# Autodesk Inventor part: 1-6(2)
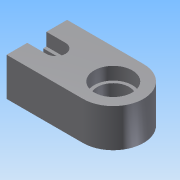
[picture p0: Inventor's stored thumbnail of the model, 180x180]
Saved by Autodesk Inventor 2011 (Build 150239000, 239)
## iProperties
Created: 2014-02
Part Number: 1-6(2)
Document SubType Name: Modeling
Designer: Administrator
Density: 1 g/cm^3
Author: Administrator
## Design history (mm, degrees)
sketch "草图1"
  geometry: L1 (-12, 9.5)-(12, 9.5); L2 (12, -9.5)-(-12, -9.5); L3 (-12, -9.5)-(-12, 9.5); A1 r 9.5 centre (12, 0) between (12, -9.5) and (12, 9.5); 3 further points
  constraints: 6 end point, 2 point on circle, 1 centre point, 1 coincident, 1 horizontal, 1 horizontal alignment, 1 midpoint, 1 parallel, 1 vertical alignment
extrude "拉伸1" new body sketch "草图1" distance "d0" = 12; taper "d1" = 0 deg
sketch "草图2"
  geometry: L1 (-12, -9.5)-(-12, 9.5) reference; L2 (-6, -2)-(-12, -2); L3 (-6, 2)-(-12, 2); A1 r 2 centre (-6, 0) between (-6, -2) and (-6, 2); 1 further point
  constraints: 4 end point, 2 perpendicular, 2 point on circle, 2 point on line, 2 tangent, 1 centre point, 1 horizontal alignment
  dimensions: "d3" = 4 diameter of A1
extrude "拉伸2" cut sketch "草图2" stored distance "d4" = 16; taper "d5" = 0 deg
sketch "草图3"
  geometry: L1 (-6, -2)-(-12, -2) reference; L2 (-12, -9.5)-(-12, -2) reference; L3 (-12, 2)-(-12, 9.5) reference; L4 (-12, 2)-(-6, 2) reference; L5 (-6, 3)-(-12, 3); L6 (-6, -3)-(-12, -3); L7 (-12, 3)-(-12, -3); A1 r 2 centre (-6, 0) between (-6, -2) and (-6, 2) reference; A2 r 3 centre (-6, 0) between (-6, -3) and (-6, 3); 1 further point
  constraints: 6 end point, 3 perpendicular, 2 point on circle, 2 point on line, 2 tangent, 1 centre point, 1 coincident
  dimensions: "d6" = 6 diameter of A2
extrude "拉伸3" cut sketch "草图3" distance "d7" = 4; taper "d8" = 0 deg
hole "Hole1" diameter "d11" = 10; stored, may be unused: countersink angle "d15" = 90 deg, drill point angle "d17" = 118 deg; dims "d9" = 10, "d10" = 10, "d12" = 6, "d13" = 4, "d14" = 2, "d16" = 8
sketch "草图4"
  geometry: C1 r 5 at (12, 0) reference; C2 r 6 at (12, 0); A1 r 9.5 centre (12, 0) between (12, -9.5) and (12, 9.5) reference; 1 further point
  constraints: 1 centre point, 1 coincident
  dimensions: "d18" = 12 diameter of C2
extrude "拉伸4" cut sketch "草图4" distance "d19" = 4; taper "d20" = 0 deg
node "实体1"
